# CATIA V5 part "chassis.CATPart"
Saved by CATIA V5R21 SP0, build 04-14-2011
Part number: Chassis
Revision: B
Nomenclature: 1
Material "Blanc": density 7860 kg/m3, Young's modulus 2e+11 Pa, Poisson ratio 0.266
Bounding box of the stored display mesh (mm): x -42 to 42, y -74 to 74, z 0 to 53
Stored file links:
  C:\Users\Olivier\Desktop\redaction CATIA (local)\CATIA\DONNEES\Exercice assemblage 1 (chassis et socle)\chassis.CATPart
  C:\Program Files\Dassault Systemes\B21\win_b64\startup\materials\French\Catalog.CATMaterial
  C:\Program Files\Dassault Systemes\B21\win_b64\startup\materials\eroded_metal_2.jpg
  C:\Program Files\Dassault Systemes\B21\win_b64\startup\materials\eroded_metal_1.jpg
  C:\Users\Olivier\Desktop\redaction CATIA (local)\pompe à moteur de ventilation refait\Pompe_a_moteur_de_ventilation.CATProduct
  C:\Users\Olivier\Desktop\redaction CATIA (local)\pompe à moteur de ventilation refait\Ecrou a collerette M5.CATPart
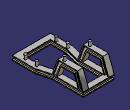
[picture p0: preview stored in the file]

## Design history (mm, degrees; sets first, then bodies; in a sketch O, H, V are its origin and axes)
Body1 (main body), material "Blanc"
  Sketch1 on yz-plane, origin (0, -62, 0), H (0, 1, 0), V (0, 0, 1)
    point P12 (0, 0)
    line L1 (0, 0) -> (-12, 0)
    line L2 (-12, 0) -> (-12, 2)
    line L3 (-12, 10) -> (0, 10)
    line L4 (0, 10) -> (0, 8)
    line L5 (-9, 2) -> (-9, 8)
    line L6 (-3, 8) -> (-3, 2)
    line L7 (0, 8) -> (-3, 8)
    line L8 (0, 2) -> (-3, 2)
    line L9 (0, 2) -> (0, 0)
    line L10 (-12, 8) -> (-12, 10)
    line L11 (-9, 8) -> (-12, 8)
    line L12 (-9, 2) -> (-12, 2)
    length L3 = 12
    length L1 = 12
    length L4 = 2
    length L6 = 6
    distance L1 L3 = 10
    length L11 = 3
    length L7 = 3
    length L12 = 3
    length L10 = 2
    length L5 = 6
    horizontal: L3 H, L7 H, L11 H, L8 H, L1 H, L12 H
    vertical: L10 V, L4 V, L6 V, L5 V, L2 V, L9 V
    coincidence: P12
  Sketch2 on xy-plane, origin (0, 0, 0), H (1, 0, 0), V (0, 1, 0)
    line L1 (-22, 62) -> (-22, 3.8564)
    line L2 (-22, 3.8564) -> (-30, -26)
    line L3 (-30, -26) -> (-30, -62)
    line L4 (-30, -62) -> (30, -62)
    line L5 (30, -62) -> (30, -26)
    line L6 (30, -26) -> (22, 3.8564)
    line L7 (22, 3.8564) -> (22, 62)
    line L8 (22, 62) -> (-22, 62)
    distance L4 H = 62
    distance L5 V = 30
    distance L8 L4 = 124
    length L5 = 36
    length L8 = 44
    length L4 = 60
    angle L6 L7 = 15
    length L3 = 36
    angle L2 L1 = 15
    vertical: L1 V, L3 V, L5 V, L7 V
    horizontal: L4 H, L8 H
    symmetry: L7 L1 V
  Rib1: profile Sketch1, centre curve Sketch2
  Sketch3 on face of Rib1, origin (0, 0, 10), H (1, 0, 0), V (0, 1, 0)
    circle A1 centre (-34, -53) radius 3
    point P1 (-34, -53)
    circle A2 centre (-34, -28) radius 3
    point P2 (-34, -28)
    circle A3 centre (34, -28) radius 3
    point P3 (34, -28)
    circle A4 centre (34, -53) radius 3
    point P4 (34, -53)
    reference projected line E1 (-42, -74) -> (42, -74) from edge [face of Rib1 | face of Rib1]
    reference projected line E2 (-42, -74) -> (42, -74) from edge [face of Rib1 | face of Rib1]
    reference projected line E3 (42, -74) -> (42, -24.4202) from edge [face of Rib1 | face of Rib1]
    construction line L1 (-34, -53) -> (-34, -28)
    construction line L2 (34, -53) -> (34, -28)
    radius A3 = 3
    radius A4 = 3
    radius A2 = 3
    radius A1 = 3
    distance E1 P4 = 21
    distance P3 P4 = 25
    distance P3 P2 = 68
    distance P1 E2 = 21
    distance P2 P1 = 25
    distance P4 E3 = 8
    vertical: L1 V, L2 V
  Pad1: profile Sketch3, direction (0, 0, 1), length 9
  Sketch4 on face of Rib1, origin (34, 0, 0), H (0, 1, 0), V (0, 0, 1)
    point P1 (74, 10)
    line L1 (74, 10) -> (61.625, 44)
    line L2 (61.625, 44) -> (17.8112, 44)
    line L3 (17.8112, 44) -> (5.4362, 10)
    point P4 (5.4362, 10)
    reference projected line E1 (5.4362, 10) -> (74, 10) from edge [face of Rib1 | face of Rib1]
    reference projected line E2 (5.4362, 10) -> (74, 10) from edge [face of Rib1 | face of Rib1]
    reference projected line E3 (74, 10) -> (74, 8) from edge [face of Rib1 | face of Rib1]
    reference projected line E4 (5.4362, 10) -> (74, 10) from edge [face of Rib1 | face of Rib1]
    reference projected line E5 (5.4362, 10) -> (5.4362, 8) from edge [face of Rib1 | face of Rib1]
    distance L2 E1 = 34
    angle L1 L2 = 70
    angle L3 L2 = 70
    horizontal: L2 H
    coincidence: P1 E2, P1 E3, P4 E4, P4 E5
  Plane1: type Normal, Curve Sketch4
  Sketch5 on Plane1, origin (0, 39.7181, 0), H (1, 0, 0), V (0, 0, 1)
    line L1 (22, 44) -> (34, 44)
    line L2 (34, 42) -> (31, 42)
    line L3 (25, 42) -> (22, 42)
    line L4 (34, 36) -> (31, 36)
    line L5 (34, 34) -> (22, 34)
    line L6 (25, 36) -> (22, 36)
    construction line L7 through (0, 0) direction (0, 1)
    line L8 (22, 42) -> (22, 44)
    line L9 (34, 44) -> (34, 42)
    line L10 (31, 42) -> (31, 36)
    line L11 (25, 36) -> (25, 42)
    line L12 (22, 34) -> (22, 36)
    line L13 (34, 36) -> (34, 34)
    point P2 (21.8717, 39.7398)
    point P5 (34, 44)
    reference projected point E1 (34, 44) from vertex [element of Sketch4 | element of Sketch4]
    length L1 = 12
    length L5 = 12
    length L9 = 2
    length L10 = 6
    length L3 = 3
    length L2 = 3
    length L6 = 3
    length L8 = 2
    length L11 = 6
    distance L5 L1 = 10
    horizontal: L1 H, L2 H, L3 H, L4 H, L5 H, L6 H
    vertical: L8 L7, L9 L7, L10 L7, L11 L7, L12 L7, L13 L7, L7 V
    coincidence: P5 E1
  Rib2: profile Sketch5, centre curve Sketch4
  Mirror1: of Rib2, Sketch4, about yz-plane
  Sketch6 on face of Rib2, origin (0, 0, 44), H (1, 0, 0), V (0, 1, 0)
    circle A1 centre (28, 26.8112) radius 3
    point P1 (28, 26.8112)
    circle A2 centre (-28, 26.8112) radius 3
    point P2 (-28, 26.8112)
    construction line L1 (-28, 26.8112) -> (28, 26.8112)
    reference projected line E1 (34, 17.8112) -> (22, 17.8112) from edge [face of Rib2 | face of Rib2]
    reference projected line E2 (34, 61.625) -> (34, 17.8112) from edge [face of Rib2 | face of Rib2]
    reference projected line E3 (-34, 61.625) -> (-34, 17.8112) from edge [face of Mirror1 | face of Mirror1]
    radius A1 = 3
    radius A2 = 3
    distance L1 E1 = 9
    distance P1 E2 = 6
    distance E3 P2 = 6
    horizontal: L1 H
  Pad2: profile Sketch6, direction (0, 0, 1), length 9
